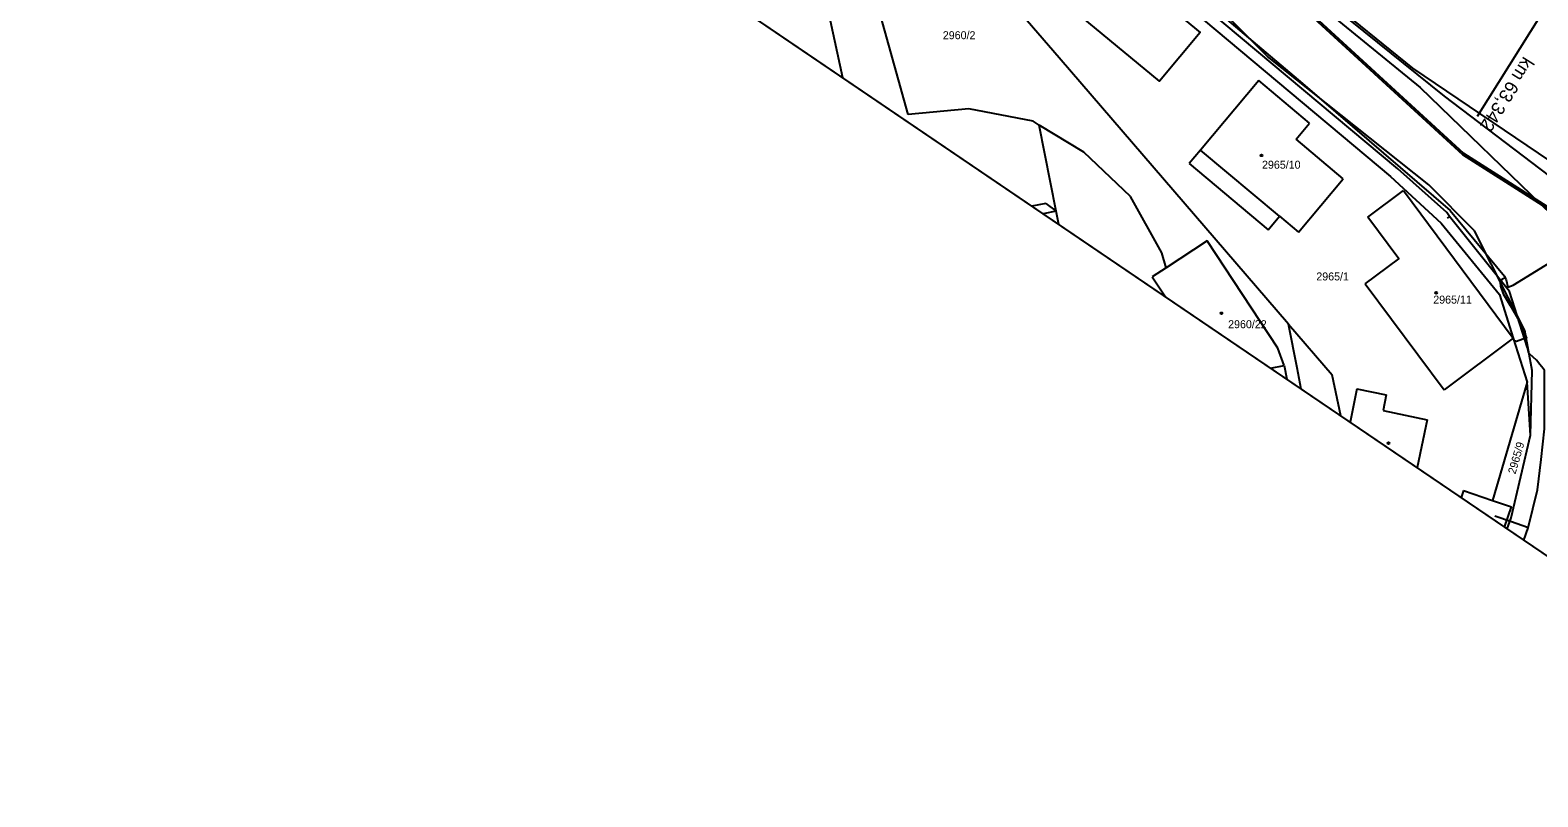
# Model space of a CAD drawing. Extents: x -621145 to -620110, y -1122807 to -1121971.
# Drawn here: x -620628.4 to -620344.9, y -1122806.7 to -1122662.4 of the extents above; entities that cross this region are included whole.
import ezdxf

# ---------------------------------------------------------------- set-up
doc = ezdxf.new("R2010")
doc.units = 0
for name, color, linetype in [('CETIN', 7, 'Continuous'), ('GasNet', 7, 'Continuous'), ('RÁMY', 7, 'Continuous'), ('SSZT-DK', 7, 'Continuous'), ('VAS vodovod', 7, 'Continuous'), ('Vrstva 55', 7, 'Continuous'), ('Vrstva 56', 7, 'Continuous'), ('Vrstva 57', 7, 'Continuous'), ('Vrstva 6', 7, 'Continuous'), ('ČD-T', 7, 'Continuous')]:
    doc.layers.add(name, color=color, linetype=linetype)

msp = doc.modelspace()

# ---------------------------------------------------------------- linework, layer by layer
at = {"layer": 'CETIN'}
msp.add_lwpolyline([(-620402.98, -1122642.16), (-620362.48, -1122674.84), (-620281.95, -1122736.09)], dxfattribs=at)
at = {"layer": 'GasNet'}
for points in [[(-620545.62, -1122586.36), (-620544.33, -1122585.86), (-620529.1, -1122581.91), (-620527.88, -1122581.68), (-620501.79, -1122593.01), (-620500.52, -1122592.53), (-620484.13, -1122585.56), (-620478.57, -1122583.14), (-620474.2, -1122586.82), (-620449.91, -1122606.86), (-620450.02, -1122607.5), (-620458.5, -1122620.02), (-620458.8, -1122620.62), (-620432.06, -1122640.49), (-620425.64, -1122643.91), (-620417.98, -1122647.99), (-620389.11, -1122672.47), (-620361.34, -1122696.38), (-620351.16, -1122708.72), (-620351, -1122709.02), (-620350.83, -1122709.39), (-620350.53, -1122710.79), (-620349.5, -1122710.44), (-620336.68, -1122702.48)], [(-620351, -1122709.02), (-620351.62, -1122709.36), (-620351.95, -1122709.89), (-620351.89, -1122710.61), (-620351.38, -1122712.06), (-620350.09, -1122714.22), (-620348.14, -1122717.64), (-620346.99, -1122720.36), (-620347.15, -1122720.39), (-620347.67, -1122720.57), (-620348.9, -1122720.99), (-620349.23, -1122720.89), (-620349.32, -1122720.93)]]:
    msp.add_lwpolyline(points, dxfattribs=at)
at = {"layer": 'RÁMY'}
for points in [[(-621061.56, -1122093.92), (-620192.94, -1122683.83), (-620276.37, -1122806.68), (-621144.99, -1122216.77)], [(-620887.83, -1122211.9), (-620192.94, -1122683.83), (-620276.37, -1122806.68), (-620971.26, -1122334.75)]]:
    msp.add_lwpolyline(points, close=True, dxfattribs=at)
at = {"layer": 'SSZT-DK'}
msp.add_lwpolyline([(-620927.29, -1122269.99), (-620900.27, -1122286.47), (-620889.15, -1122293.45), (-620783.74, -1122358.82), (-620712.75, -1122398.18), (-620653.12, -1122435.23), (-620617.36, -1122456.74), (-620574.42, -1122482.6), (-620528.16, -1122511.11), (-620496.31, -1122530.83), (-620515.02, -1122558.81), (-620500.38, -1122568.61), (-620465.39, -1122591.45), (-620452.16, -1122605.02), (-620438.23, -1122615.5), (-620392.31, -1122655.21), (-620359.04, -1122685.8), (-620308.77, -1122717.8), (-620291.41, -1122732.21), (-620277.2, -1122744.11), (-620257.61, -1122720.05), (-620250.25, -1122710.72), (-620233.29, -1122724.26), (-620225.35, -1122731.56)], dxfattribs=at)
at = {"layer": 'VAS vodovod'}
for points in [[(-620346.78, -1122722.2), (-620350.17, -1122711.62), (-620361.5, -1122697.5), (-620361.99, -1122696.76), (-620371.19, -1122688.51), (-620418.43, -1122648.88), (-620439.22, -1122636.74), (-620439.29, -1122636.69), (-620439.37, -1122636.64), (-620460.46, -1122621.06), (-620460.7, -1122620.9), (-620459.95, -1122619.77), (-620451.51, -1122607.79), (-620450.89, -1122606.96), (-620476.53, -1122586.08), (-620476.53, -1122586.08), (-620476.87, -1122585.61)], [(-620361.87, -1122697.82), (-620361.59, -1122697.59), (-620361.5, -1122697.5)], [(-620347.51, -1122758.36), (-620346.67, -1122756.05), (-620345.79, -1122752.48), (-620344.9, -1122748.91), (-620344.25, -1122743.18), (-620343.6, -1122737.45), (-620343.6, -1122731.96), (-620343.61, -1122726.46), (-620343.74, -1122726.27), (-620343.87, -1122726.08), (-620344.48, -1122725.31), (-620345.09, -1122724.54), (-620345.76, -1122723.95), (-620346.43, -1122723.35), (-620346.44, -1122723.33), (-620346.48, -1122723.26), (-620346.53, -1122723.17), (-620346.66, -1122722.69), (-620346.78, -1122722.2)], [(-620346.67, -1122756.05), (-620346.82, -1122756), (-620349.82, -1122754.95), (-620352.97, -1122753.85)]]:
    msp.add_lwpolyline(points, dxfattribs=at)
at = {"layer": 'Vrstva 55'}
for p, q in [((-620466.94, -1122589.51), (-620368.46, -1122669.58)), ((-620463.28, -1122678.3), (-620478.32, -1122624.38)), ((-620434.88, -1122667.63), (-620473.14, -1122623.15)), ((-620475.57, -1122671.39), (-620485.31, -1122626.04)), ((-620420.38, -1122629.64), (-620366.98, -1122673.23)), ((-620395.68, -1122667.41), (-620404.9, -1122658.18)), ((-620391.77, -1122717.74), (-620434.88, -1122667.63)), ((-620365.35, -1122691.52), (-620395.68, -1122667.41)), ((-620368.46, -1122669.58), (-620310.57, -1122708.76)), ((-620397.34, -1122671.88), (-620408.32, -1122685)), ((-620387.77, -1122679.92), (-620397.34, -1122671.88)), ((-620366.98, -1122673.23), (-620342.37, -1122697.07)), ((-620451.85, -1122677.25), (-620463.28, -1122678.3)), ((-620439.78, -1122679.56), (-620451.85, -1122677.25)), ((-620438.61, -1122680.28), (-620439.78, -1122679.56)), ((-620435.41, -1122696.52), (-620438.61, -1122680.28)), ((-620430.21, -1122685.42), (-620438.61, -1122680.28)), ((-620390.32, -1122682.97), (-620387.77, -1122679.92)), ((-620381.44, -1122690.4), (-620390.32, -1122682.97)), ((-620421.46, -1122693.76), (-620430.21, -1122685.42)), ((-620408.32, -1122685), (-620410.45, -1122687.55)), ((-620410.45, -1122687.55), (-620395.56, -1122700.01)), ((-620389.88, -1122700.43), (-620381.44, -1122690.4)), ((-620376.85, -1122697.59), (-620370.13, -1122692.59)), ((-620370.13, -1122692.59), (-620349.5, -1122720.4)), ((-620356.78, -1122700.2), (-620365.35, -1122691.52)), ((-620415.57, -1122704.35), (-620421.46, -1122693.76)), ((-620435.41, -1122696.52), (-620437.86, -1122697)), ((-620434.92, -1122699), (-620435.41, -1122696.52)), ((-620395.56, -1122700.01), (-620393.43, -1122697.46)), ((-620393.43, -1122697.46), (-620389.88, -1122700.43)), ((-620347.29, -1122718.92), (-620356.78, -1122700.2)), ((-620414.76, -1122707.13), (-620415.57, -1122704.35)), ((-620407.04, -1122702.06), (-620414.76, -1122707.13)), ((-620393.75, -1122722.26), (-620407.04, -1122702.06)), ((-620414.76, -1122707.13), (-620417.37, -1122708.84)), ((-620417.37, -1122708.84), (-620414.89, -1122712.61)), ((-620377.36, -1122710.19), (-620362.45, -1122730.09)), ((-620391.77, -1122717.74), (-620383.57, -1122727.26)), ((-620390.13, -1122725.98), (-620391.77, -1122717.74)), ((-620345.94, -1122726.44), (-620347.29, -1122718.92)), ((-620349.5, -1122720.4), (-620362.45, -1122730.09)), ((-620349.5, -1122720.4), (-620346.9, -1122728.66)), ((-620392.56, -1122725.51), (-620393.75, -1122722.26)), ((-620395.15, -1122726.01), (-620392.56, -1122725.51)), ((-620392.56, -1122725.51), (-620392.06, -1122728.11)), ((-620389.35, -1122729.95), (-620390.13, -1122725.98)), ((-620381.9, -1122735.01), (-620383.57, -1122727.26)), ((-620346.26, -1122738.61), (-620345.94, -1122726.44)), ((-620378.87, -1122729.94), (-620380.18, -1122736.18)), ((-620378.87, -1122729.94), (-620373.38, -1122731.07)), ((-620346.9, -1122728.66), (-620353.41, -1122750.9)), ((-620346.26, -1122738.61), (-620346.9, -1122728.66)), ((-620373.38, -1122731.07), (-620373.97, -1122734.01)), ((-620373.97, -1122734.01), (-620365.7, -1122735.74)), ((-620365.7, -1122735.74), (-620367.58, -1122744.74)), ((-620349.91, -1122754.18), (-620346.26, -1122738.61)), ((-620358.86, -1122749.03), (-620359.31, -1122750.35)), ((-620358.86, -1122749.03), (-620353.41, -1122750.9)), ((-620353.41, -1122750.9), (-620349.8, -1122752.13)), ((-620351.12, -1122755.91), (-620349.8, -1122752.13)), ((-620350.63, -1122756.24), (-620349.91, -1122754.18))]:
    msp.add_line(p, q, dxfattribs=at)
for points in [[(-620432.38, -1122643.03), (-620419.73, -1122650.41), (-620372.55, -1122689.97), (-620363.06, -1122698.75), (-620352.08, -1122712.18), (-620349.5, -1122720.4)], [(-620434.7, -1122656.53), (-620427.07, -1122647.39), (-620408.37, -1122662.86), (-620416.01, -1122672.06), (-620434.7, -1122656.53)], [(-620377.36, -1122710.19), (-620370.99, -1122705.44), (-620376.85, -1122697.59)]]:
    msp.add_lwpolyline(points, dxfattribs=at)
at = {"layer": 'Vrstva 56'}
for p, q in [((-620393.43, -1122697.46), (-620408.32, -1122685)), ((-620437.36, -1122695.04), (-620439.99, -1122695.56)), ((-620437.36, -1122695.04), (-620435.41, -1122696.52))]:
    msp.add_line(p, q, dxfattribs=at)
at = {"layer": 'Vrstva 57'}
for centre in [(-620396.83, -1122685.99), (-620363.99, -1122711.85), (-620404.37, -1122715.7), (-620372.96, -1122740.15)]:
    msp.add_circle(centre, 0.175, dxfattribs=at)
at = {"layer": 'Vrstva 6'}
msp.add_line((-620344.27, -1122659.46), (-620356.26, -1122678.68), dxfattribs=at)
at = {"layer": 'ČD-T'}
msp.add_lwpolyline([(-620927.12, -1122269.75), (-620900.08, -1122286.23), (-620888.96, -1122293.22), (-620783.56, -1122358.58), (-620712.56, -1122397.94), (-620652.93, -1122435), (-620617.18, -1122456.5), (-620574.24, -1122482.37), (-620527.97, -1122510.87), (-620481.08, -1122540.08), (-620497, -1122565.38), (-620499.27, -1122568.98), (-620465.21, -1122591.22), (-620451.97, -1122604.79), (-620438.05, -1122615.26), (-620392.12, -1122654.98), (-620358.85, -1122685.56), (-620308.58, -1122717.56), (-620291.22, -1122731.97), (-620279.98, -1122741.46), (-620260.48, -1122717.47), (-620252.94, -1122708.19), (-620233.1, -1122724.03), (-620225.18, -1122731.31)], dxfattribs=at)

# ---------------------------------------------------------------- texts
at = {"layer": 'Vrstva 57'}
for s, p in [('2960/2', (-620456.75, -1122664.14)), ('2965/10', (-620396.73, -1122688.5)), ('2965/1', (-620386.52, -1122709.52)), ('2965/11', (-620364.53, -1122713.88)), ('2960/22', (-620403.1, -1122718.51))]:
    msp.add_text(s, height=1.5, dxfattribs=at).set_placement(p)
msp.add_text('2965/9', height=1.5, rotation=73.8221, dxfattribs=at).set_placement((-620349.08, -1122746.06))
at = {"layer": 'Vrstva 6'}
msp.add_text('km 63,342', height=2.5, rotation=237.7824, dxfattribs=at).set_placement((-620347.53, -1122667.24))

doc.saveas('drawing.dxf')
